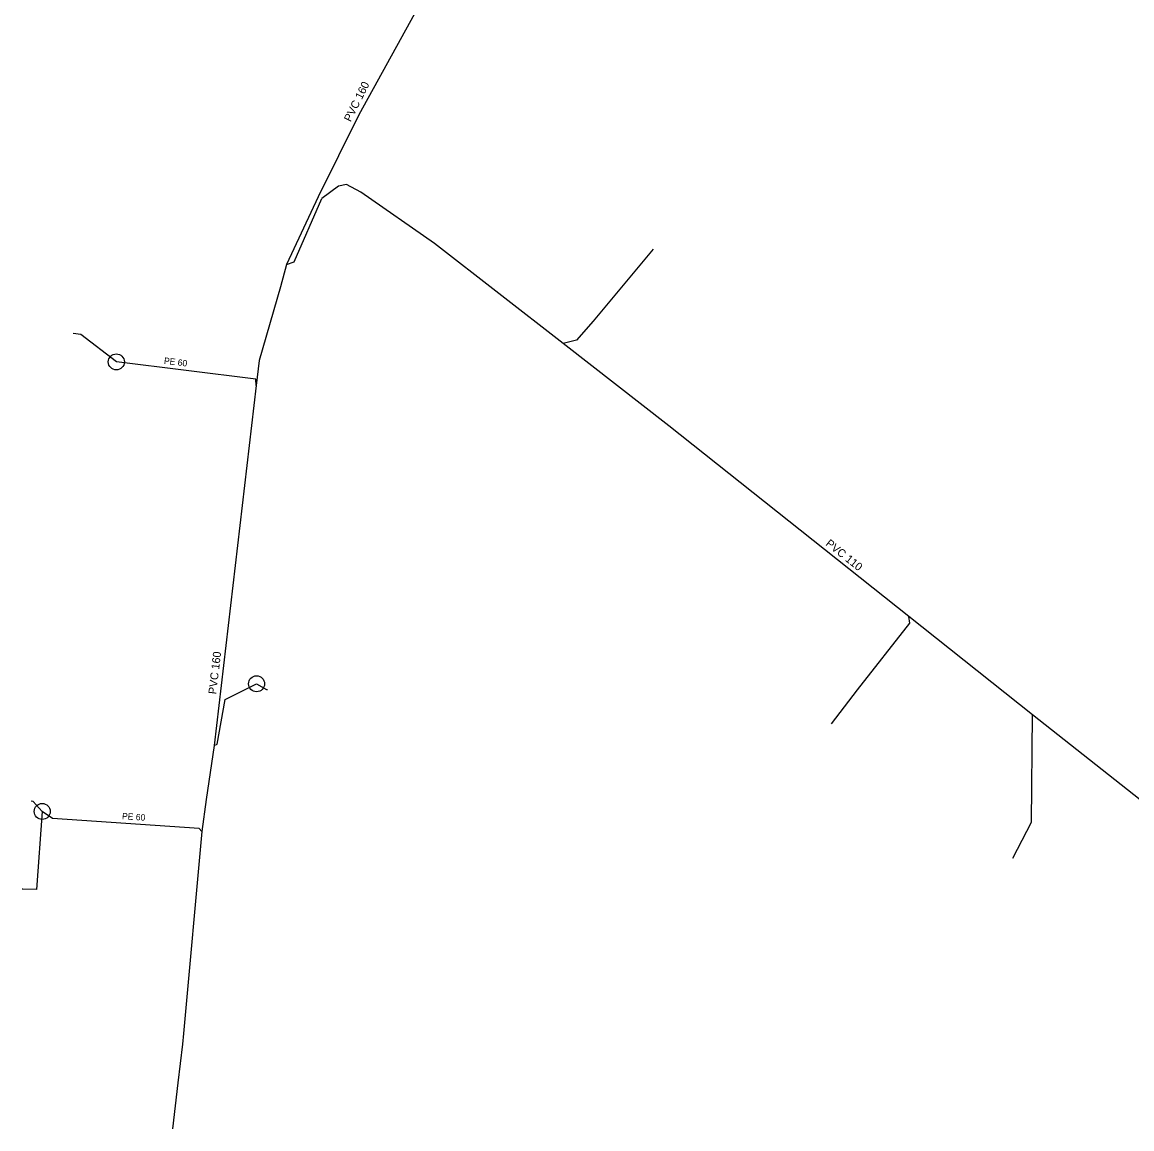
# Model space of a CAD drawing. Extents: x -687195 to -686827, y -1053873 to -1053627.
# Drawn here: x -687079.7 to -687010.4, y -1053872.6 to -1053803.5 of the extents above; entities that cross this region are included whole.
import ezdxf

# ---------------------------------------------------------------- set-up
doc = ezdxf.new("R2010")
doc.units = 0
for name, color, linetype in [('Kanalizační přípojky', 7, 'Continuous'), ('Kanalizační stoka', 7, 'Continuous'), ('Kanalizační šachty', 7, 'Continuous'), ('Popis', 7, 'Continuous')]:
    doc.layers.add(name, color=color, linetype=linetype)

msp = doc.modelspace()

# ---------------------------------------------------------------- linework, layer by layer
at = {"layer": 'Kanalizační přípojky'}
for points in [[(-687040.32, -1053817.69), (-687044.08, -1053822.19)], [(-687044.08, -1053822.19), (-687045.11, -1053823.38), (-687045.96, -1053823.59)], [(-687065.12, -1053826.22), (-687065.15, -1053825.82), (-687073.86, -1053824.74), (-687076.08, -1053823.02), (-687076.55, -1053822.97)], [(-687027.57, -1053845.23), (-687024.29, -1053841.07), (-687024.36, -1053840.65)], [(-687067.74, -1053848.7), (-687067.56, -1053848.62), (-687067.07, -1053845.84), (-687065.1, -1053844.85), (-687064.49, -1053845.2), (-687064.42, -1053845.21)], [(-687029.2, -1053847.35), (-687027.57, -1053845.23)], [(-687016.7, -1053853.5), (-687016.63, -1053846.79)], [(-687078.49, -1053852.82), (-687079.06, -1053852.2), (-687079.18, -1053852.19)], [(-687078.49, -1053852.82), (-687078.84, -1053857.69), (-687079.71, -1053857.67), (-687079.74, -1053857.67)], [(-687068.53, -1053854.08), (-687068.68, -1053853.89), (-687077.85, -1053853.26), (-687078.49, -1053852.82)], [(-687017.87, -1053855.74), (-687016.7, -1053853.5)]]:
    msp.add_lwpolyline(points, dxfattribs=at)
at = {"layer": 'Kanalizační stoka'}
for points in [[(-687054.34, -1053801.35), (-687058.71, -1053809.31), (-687061.25, -1053814.42), (-687063.24, -1053818.66)], [(-686999, -1053860.72), (-687001.6, -1053858.66), (-687016.63, -1053846.79), (-687024.36, -1053840.65), (-687039.36, -1053828.73), (-687045.96, -1053823.59), (-687053.98, -1053817.34), (-687058.59, -1053814.13), (-687059.48, -1053813.66), (-687059.98, -1053813.77), (-687061.02, -1053814.54)], [(-687063.24, -1053818.66), (-687062.76, -1053818.5), (-687061.02, -1053814.54)], [(-687063.24, -1053818.66), (-687063.61, -1053820.05), (-687064.94, -1053824.66), (-687065.12, -1053826.22), (-687067.74, -1053848.7), (-687068.24, -1053852.08), (-687068.53, -1053854.08), (-687069.67, -1053866.69), (-687069.73, -1053867.36), (-687070.02, -1053869.78), (-687070.361, -1053872.649)]]:
    msp.add_lwpolyline(points, dxfattribs=at)
at = {"layer": 'Kanalizační šachty'}
for centre in [(-687073.86, -1053824.74), (-687065.1, -1053844.85), (-687078.49, -1053852.82)]:
    msp.add_circle(centre, 0.5, dxfattribs=at)

# ---------------------------------------------------------------- texts
at = {"layer": 'Popis'}
for s, height, rotation, p in [('PVC 160', 0.5, 63.56966, (-687059.225, -1053809.785)), ('PE 60', 0.4, 352.93166, (-687070.903, -1053824.855)), ('PVC 110', 0.5, 321.527, (-687029.599, -1053836.167)), ('PVC 160', 0.5, 83.35228, (-687067.621, -1053845.522)), ('PE 60', 0.4, 356.06982, (-687073.515, -1053853.307))]:
    msp.add_text(s, height=height, rotation=rotation, dxfattribs=at).set_placement(p)

doc.saveas('drawing.dxf')
